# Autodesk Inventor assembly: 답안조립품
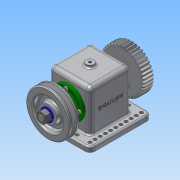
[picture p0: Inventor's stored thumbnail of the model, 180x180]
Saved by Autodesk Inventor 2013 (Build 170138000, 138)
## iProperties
Created: 2018-11
Part Number: 답안조립품
Document SubType Name: Assembly
Designer: Administrator
Author: Administrator
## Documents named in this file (13)
- C:\Users\Administrator\Desktop\481107V1005\답안조립품.iam
- C:\Users\Administrator\Desktop\481107V1005\본체.ipt
- C:\Users\Administrator\Desktop\481107V1005\V벨트풀리.ipt
- C:\Users\Administrator\Desktop\481107V1005\너트 M12x1.25.ipt
- C:\Users\Administrator\Desktop\481107V1005\베어링 6203.ipt
- C:\Users\Administrator\Desktop\481107V1005\볼트 M4.ipt
- C:\Users\Administrator\Desktop\481107V1005\부시.ipt
- C:\Users\Administrator\Desktop\481107V1005\스퍼기어.ipt
- C:\Users\Administrator\Desktop\481107V1005\오일 실 26 38 8.ipt
- C:\Users\Administrator\Desktop\481107V1005\와셔 12x24.ipt
- C:\Users\Administrator\Desktop\481107V1005\축.ipt
- C:\Users\Administrator\Desktop\481107V1005\커버.ipt
- C:\Users\Administrator\Desktop\481107V1005\키 5x5x12.ipt
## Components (1 placed, 1 different names)
1. V벨트풀리:1
